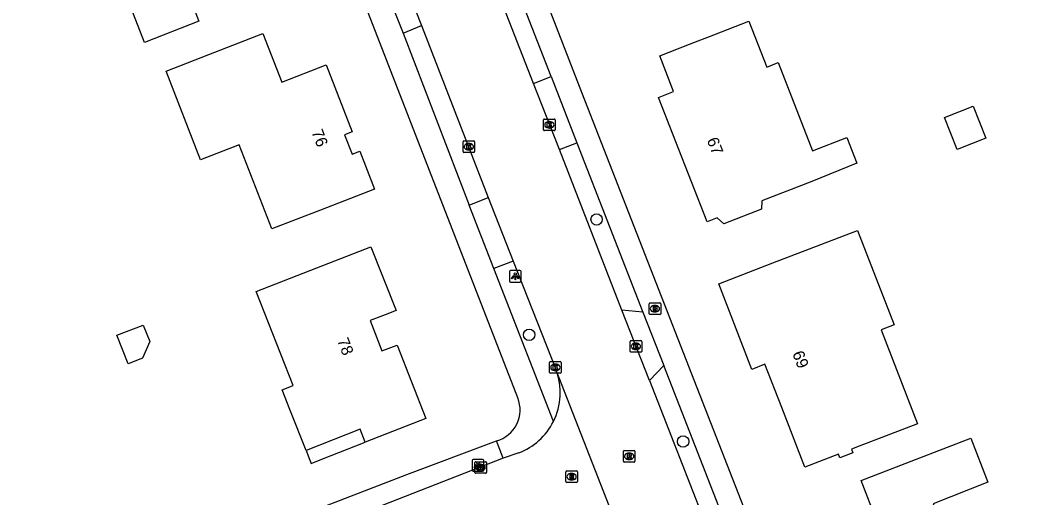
# Model space of a CAD drawing. Extents: x 157321 to 158827, y 386650 to 388532.
# Drawn here: x 158167.1 to 158253.3, y 387023.2 to 387064.3 of the extents above; entities that cross this region are included whole.
import ezdxf

# ---------------------------------------------------------------- set-up
doc = ezdxf.new("R2010")
doc.units = 0
for name, color, linetype in [('IMGEO_Boom', 7, 'Continuous'), ('IMGEO_Brandkraan', 7, 'Continuous'), ('IMGEO_Groenvoorziening', 7, 'Continuous'), ('IMGEO_Hek', 7, 'Continuous'), ('IMGEO_Kolk', 7, 'Continuous'), ('IMGEO_Lichtpunt', 7, 'Continuous'), ('IMGEO_Pand', 7, 'Continuous'), ('IMGEO_Pand_nummerreeks', 7, 'Continuous'), ('IMGEO_Pand_overbouw', 7, 'Continuous'), ('IMGEO_Rijbaan_lokaal_gesloten', 7, 'Continuous'), ('IMGEO_Rioolput', 7, 'Continuous'), ('IMGEO_Voetpad_open', 7, 'Continuous')]:
    doc.layers.add(name, color=color, linetype=linetype)

msp = doc.modelspace()

# ---------------------------------------------------------------- linework, layer by layer
at = {"layer": 'IMGEO_Boom'}
for centre in [(158216.746, 387047.149), (158210.932, 387037.217), (158224.196, 387028.029)]:
    msp.add_circle(centre, 0.489, dxfattribs=at)
at = {"layer": 'IMGEO_Brandkraan'}
for p, q in [((158221.265, 387039.034), (158221.265, 387039.886)), ((158221.34, 387039.96), (158222.192, 387039.96)), ((158221.753, 387039.74), (158221.778, 387039.74)), ((158222.266, 387039.886), (158222.266, 387039.034)), ((158222.192, 387038.96), (158221.34, 387038.96)), ((158221.776, 387039.18), (158221.751, 387039.18))]:
    msp.add_line(p, q, dxfattribs=at)
for points in [[(158221.265, 387039.034), (158221.265, 387039.886)], [(158221.34, 387039.96), (158222.192, 387039.96)], [(158221.613, 387039.66), (158221.613, 387039.26), (158221.826, 387039.26)], [(158221.844, 387039.66), (158221.613, 387039.66)], [(158221.792, 387039.579), (158221.738, 387039.579), (158221.738, 387039.503)], [(158221.738, 387039.503), (158221.791, 387039.503)], [(158221.8, 387039.427), (158221.738, 387039.427), (158221.738, 387039.346)], [(158222.266, 387039.886), (158222.266, 387039.034)], [(158222.192, 387038.96), (158221.34, 387038.96)], [(158221.738, 387039.346), (158221.8, 387039.346)]]:
    msp.add_lwpolyline(points, dxfattribs=at)
for centre, radius, start, end in [((158221.342, 387039.884), 0.0765, 91.55205, 178.44795), ((158221.342, 387039.884), 0.0765, 91.55205, 178.44795), ((158221.793, 387039.541), 0.0379, 267.82845, 90.93552), ((158221.801, 387039.386), 0.0404, 269.87594, 90.50774), ((158221.848, 387039.515), 0.145, 59.4692, 91.53667), ((158221.873, 387039.562), 0.0922, 285.51372, 58.15012), ((158221.878, 387039.37), 0.105, 301.31148, 78.98903), ((158222.19, 387039.884), 0.0765, 1.55205, 88.44795), ((158222.19, 387039.884), 0.0765, 1.55205, 88.44795), ((158221.342, 387039.036), 0.0765, 181.55205, 268.44795), ((158221.342, 387039.036), 0.0765, 181.55205, 268.44795), ((158221.832, 387039.511), 0.251, 268.66757, 293.53466), ((158222.19, 387039.036), 0.0765, 271.55205, 358.44795), ((158222.19, 387039.036), 0.0765, 271.55205, 358.44795)]:
    msp.add_arc(centre, radius, start, end, dxfattribs=at)
for centre, major_axis, ratio, start_param, end_param in [((158221.752, 387039.46), (-0.387, 0.002), 0.722429, 4.712389, 7.853982), ((158221.777, 387039.46), (-0.39, 0.002), 0.717154, 1.570796, 4.712389)]:
    msp.add_ellipse(centre, major_axis=major_axis, ratio=ratio, start_param=start_param, end_param=end_param, dxfattribs=at)
at = {"layer": 'IMGEO_Groenvoorziening'}
msp.add_lwpolyline([(158164.275, 387011.156), (158171.314, 387013.97), (158200.402, 387025.18), (158208.12, 387028.081)], dxfattribs=at)
at = {"layer": 'IMGEO_Hek'}
for points in [[(158200.402, 387025.18), (158208.12, 387028.081)], [(158171.314, 387013.97), (158200.402, 387025.18)]]:
    msp.add_lwpolyline(points, dxfattribs=at)
at = {"layer": 'IMGEO_Kolk'}
for p, q in [((158212.249, 387055.797), (158213.101, 387055.797)), ((158212.174, 387054.871), (158212.174, 387055.723)), ((158212.685, 387055.017), (158212.66, 387055.017)), ((158212.662, 387055.577), (158212.687, 387055.577)), ((158213.175, 387055.723), (158213.175, 387054.871)), ((158213.101, 387054.797), (158212.249, 387054.797)), ((158205.238, 387052.986), (158205.238, 387053.838)), ((158205.313, 387053.912), (158206.165, 387053.912)), ((158205.726, 387053.692), (158205.751, 387053.692)), ((158206.239, 387053.838), (158206.239, 387052.986)), ((158206.165, 387052.912), (158205.313, 387052.912)), ((158205.749, 387053.132), (158205.724, 387053.132)), ((158219.632, 387035.79), (158219.632, 387036.642)), ((158219.707, 387036.716), (158220.559, 387036.716)), ((158220.143, 387035.936), (158220.118, 387035.936)), ((158220.12, 387036.496), (158220.145, 387036.496)), ((158220.633, 387036.642), (158220.633, 387035.79)), ((158220.559, 387035.716), (158219.707, 387035.716)), ((158212.691, 387033.979), (158212.691, 387034.831)), ((158212.766, 387034.905), (158213.618, 387034.905)), ((158213.179, 387034.685), (158213.204, 387034.685)), ((158213.692, 387034.831), (158213.692, 387033.979)), ((158213.618, 387033.905), (158212.766, 387033.905)), ((158213.202, 387034.125), (158213.177, 387034.125)), ((158206.249, 387025.359), (158206.249, 387026.211)), ((158206.324, 387026.285), (158207.176, 387026.285)), ((158206.737, 387026.065), (158206.762, 387026.065)), ((158207.25, 387026.211), (158207.25, 387025.359)), ((158207.176, 387025.285), (158206.324, 387025.285)), ((158206.76, 387025.505), (158206.735, 387025.505))]:
    msp.add_line(p, q, dxfattribs=at)
for points in [[(158212.249, 387055.797), (158213.101, 387055.797)], [(158212.174, 387054.871), (158212.174, 387055.723)], [(158212.495, 387055.497), (158212.618, 387055.497), (158212.618, 387055.346), (158212.748, 387055.497), (158212.912, 387055.497), (158212.766, 387055.346), (158212.919, 387055.097), (158212.767, 387055.097), (158212.682, 387055.261), (158212.618, 387055.194), (158212.618, 387055.097), (158212.495, 387055.097), (158212.495, 387055.497)], [(158213.175, 387055.723), (158213.175, 387054.871)], [(158213.101, 387054.797), (158212.249, 387054.797)], [(158205.238, 387052.986), (158205.238, 387053.838)], [(158205.313, 387053.912), (158206.165, 387053.912)], [(158205.559, 387053.612), (158205.682, 387053.612), (158205.682, 387053.461), (158205.812, 387053.612), (158205.976, 387053.612), (158205.83, 387053.461), (158205.983, 387053.212), (158205.831, 387053.212), (158205.746, 387053.376), (158205.682, 387053.309), (158205.682, 387053.212), (158205.559, 387053.212), (158205.559, 387053.612)], [(158206.239, 387053.838), (158206.239, 387052.986)], [(158206.165, 387052.912), (158205.313, 387052.912)], [(158219.632, 387035.79), (158219.632, 387036.642)], [(158219.707, 387036.716), (158220.559, 387036.716)], [(158219.953, 387036.416), (158220.076, 387036.416), (158220.076, 387036.265), (158220.206, 387036.416), (158220.37, 387036.416), (158220.224, 387036.265), (158220.377, 387036.016), (158220.225, 387036.016), (158220.14, 387036.18), (158220.076, 387036.113), (158220.076, 387036.016), (158219.953, 387036.016), (158219.953, 387036.416)], [(158220.633, 387036.642), (158220.633, 387035.79)], [(158220.559, 387035.716), (158219.707, 387035.716)], [(158212.691, 387033.979), (158212.691, 387034.831)], [(158212.766, 387034.905), (158213.618, 387034.905)], [(158213.012, 387034.605), (158213.135, 387034.605), (158213.135, 387034.454), (158213.265, 387034.605), (158213.429, 387034.605), (158213.283, 387034.454), (158213.436, 387034.205), (158213.284, 387034.205), (158213.199, 387034.369), (158213.135, 387034.302), (158213.135, 387034.205), (158213.012, 387034.205), (158213.012, 387034.605)], [(158213.692, 387034.831), (158213.692, 387033.979)], [(158213.618, 387033.905), (158212.766, 387033.905)], [(158206.249, 387025.359), (158206.249, 387026.211)], [(158206.324, 387026.285), (158207.176, 387026.285)], [(158206.57, 387025.985), (158206.693, 387025.985), (158206.693, 387025.834), (158206.823, 387025.985), (158206.987, 387025.985), (158206.841, 387025.834), (158206.994, 387025.585), (158206.842, 387025.585), (158206.757, 387025.749), (158206.693, 387025.682), (158206.693, 387025.585), (158206.57, 387025.585), (158206.57, 387025.985)], [(158207.25, 387026.211), (158207.25, 387025.359)], [(158207.176, 387025.285), (158206.324, 387025.285)]]:
    msp.add_lwpolyline(points, dxfattribs=at)
for centre, start, end in [((158212.251, 387055.721), 91.55205, 178.44795), ((158212.251, 387055.721), 91.55205, 178.44795), ((158213.099, 387055.721), 1.55205, 88.44795), ((158213.099, 387055.721), 1.55205, 88.44795), ((158212.251, 387054.873), 181.55205, 268.44795), ((158212.251, 387054.873), 181.55205, 268.44795), ((158213.099, 387054.873), 271.55205, 358.44795), ((158213.099, 387054.873), 271.55205, 358.44795), ((158205.315, 387053.836), 91.55205, 178.44795), ((158205.315, 387053.836), 91.55205, 178.44795), ((158206.163, 387053.836), 1.55205, 88.44795), ((158206.163, 387053.836), 1.55205, 88.44795), ((158205.315, 387052.988), 181.55205, 268.44795), ((158205.315, 387052.988), 181.55205, 268.44795), ((158206.163, 387052.988), 271.55205, 358.44795), ((158206.163, 387052.988), 271.55205, 358.44795), ((158219.709, 387036.64), 91.55205, 178.44795), ((158219.709, 387036.64), 91.55205, 178.44795), ((158220.557, 387036.64), 1.55205, 88.44795), ((158220.557, 387036.64), 1.55205, 88.44795), ((158219.709, 387035.792), 181.55205, 268.44795), ((158219.709, 387035.792), 181.55205, 268.44795), ((158220.557, 387035.792), 271.55205, 358.44795), ((158220.557, 387035.792), 271.55205, 358.44795), ((158212.768, 387034.829), 91.55205, 178.44795), ((158212.768, 387034.829), 91.55205, 178.44795), ((158213.616, 387034.829), 1.55205, 88.44795), ((158213.616, 387034.829), 1.55205, 88.44795), ((158212.768, 387033.981), 181.55205, 268.44795), ((158212.768, 387033.981), 181.55205, 268.44795), ((158213.616, 387033.981), 271.55205, 358.44795), ((158213.616, 387033.981), 271.55205, 358.44795), ((158206.326, 387026.209), 91.55205, 178.44795), ((158206.326, 387026.209), 91.55205, 178.44795), ((158207.174, 387026.209), 1.55205, 88.44795), ((158207.174, 387026.209), 1.55205, 88.44795), ((158206.326, 387025.361), 181.55205, 268.44795), ((158206.326, 387025.361), 181.55205, 268.44795), ((158207.174, 387025.361), 271.55205, 358.44795), ((158207.174, 387025.361), 271.55205, 358.44795)]:
    msp.add_arc(centre, 0.0765, start, end, dxfattribs=at)
for centre, major_axis, ratio, start_param, end_param in [((158212.661, 387055.297), (-0.387, 0.002), 0.722429, 4.712389, 7.853982), ((158212.686, 387055.297), (-0.39, 0.002), 0.717154, 1.570796, 4.712389), ((158205.725, 387053.412), (-0.387, 0.002), 0.722429, 4.712389, 7.853982), ((158205.75, 387053.412), (-0.39, 0.002), 0.717154, 1.570796, 4.712389), ((158220.119, 387036.216), (-0.387, 0.002), 0.722429, 4.712389, 7.853982), ((158220.144, 387036.216), (-0.39, 0.002), 0.717154, 1.570796, 4.712389), ((158213.178, 387034.405), (-0.387, 0.002), 0.722429, 4.712389, 7.853982), ((158213.203, 387034.405), (-0.39, 0.002), 0.717154, 1.570796, 4.712389), ((158206.736, 387025.785), (-0.387, 0.002), 0.722429, 4.712389, 7.853982), ((158206.761, 387025.785), (-0.39, 0.002), 0.717154, 1.570796, 4.712389)]:
    msp.add_ellipse(centre, major_axis=major_axis, ratio=ratio, start_param=start_param, end_param=end_param, dxfattribs=at)
at = {"layer": 'IMGEO_Lichtpunt'}
for p, q in [((158209.241, 387042.655), (158209.241, 387041.848)), ((158209.241, 387042.655), (158209.241, 387041.848)), ((158210.143, 387042.75), (158209.335, 387042.75)), ((158210.143, 387042.75), (158209.335, 387042.75)), ((158210.237, 387041.848), (158210.237, 387042.655)), ((158210.237, 387041.848), (158210.237, 387042.655)), ((158209.335, 387041.754), (158210.143, 387041.754)), ((158209.335, 387041.754), (158210.143, 387041.754)), ((158206.924, 387026.474), (158206.116, 387026.474)), ((158206.924, 387026.474), (158206.116, 387026.474)), ((158206.022, 387026.379), (158206.022, 387025.572)), ((158206.022, 387026.379), (158206.022, 387025.572)), ((158207.018, 387025.572), (158207.018, 387026.379)), ((158207.018, 387025.572), (158207.018, 387026.379)), ((158206.116, 387025.478), (158206.924, 387025.478)), ((158206.116, 387025.478), (158206.924, 387025.478))]:
    msp.add_line(p, q, dxfattribs=at)
for points in [[(158209.615, 387042.319), (158209.654, 387042.291), (158209.466, 387042.029), (158209.428, 387042.056), (158209.615, 387042.319)], [(158209.717, 387042.271), (158209.764, 387042.271), (158209.764, 387041.949), (158209.717, 387041.949), (158209.717, 387042.271)], [(158209.827, 387042.291), (158209.865, 387042.318), (158210.052, 387042.056), (158210.013, 387042.028), (158209.827, 387042.291)], [(158206.396, 387026.043), (158206.435, 387026.015), (158206.247, 387025.753), (158206.209, 387025.78), (158206.396, 387026.043)], [(158206.498, 387025.995), (158206.545, 387025.995), (158206.545, 387025.673), (158206.498, 387025.673), (158206.498, 387025.995)], [(158206.608, 387026.015), (158206.646, 387026.042), (158206.833, 387025.78), (158206.794, 387025.752), (158206.608, 387026.015)]]:
    msp.add_lwpolyline(points, dxfattribs=at)
for centre in [(158209.74, 387042.453), (158206.521, 387026.177)]:
    msp.add_circle(centre, 0.0994, dxfattribs=at)
for centre, start, end in [((158209.335, 387042.655), 90, 180), ((158209.335, 387042.655), 90, 180), ((158210.143, 387042.655), 0, 90), ((158210.143, 387042.655), 0, 90), ((158209.335, 387041.848), 180, 270), ((158209.335, 387041.848), 180, 270), ((158210.143, 387041.848), 270, 0), ((158210.143, 387041.848), 270, 360), ((158206.116, 387026.379), 90, 180), ((158206.116, 387026.379), 90, 180), ((158206.924, 387026.379), 0, 90), ((158206.924, 387026.379), 0, 90), ((158206.116, 387025.572), 180, 270), ((158206.116, 387025.572), 180, 270), ((158206.924, 387025.572), 270, 0), ((158206.924, 387025.572), 270, 360)]:
    msp.add_arc(centre, 0.0946, start, end, dxfattribs=at)
at = {"layer": 'IMGEO_Pand'}
for points in [[(158180.919, 387079.128), (158182.888, 387074.067), (158187.406, 387075.824), (158188.819, 387072.194), (158187.699, 387071.753), (158189.187, 387067.922), (158184.527, 387066.11), (158182.102, 387065.167), (158182.475, 387064.21), (158177.811, 387062.396), (158175.705, 387067.813), (158177.358, 387068.456), (158174.221, 387076.522), (158176.26, 387077.315), (158180.919, 387079.128)], [(158239.172, 387051.986), (158235.27, 387050.43), (158230.972, 387048.764), (158230.945, 387048.036), (158227.7, 387046.757), (158227.144, 387047.28), (158226.275, 387046.944), (158223.573, 387053.843), (158222.078, 387057.659), (158223.374, 387058.161), (158222.182, 387061.247), (158224.757, 387062.242), (158226.847, 387063.049), (158229.87, 387064.217), (158231.416, 387060.27), (158232.386, 387060.651), (158235.353, 387053.05), (158238.306, 387054.203), (158239.172, 387051.986)], [(158179.653, 387059.92), (158183.344, 387061.351), (158188.005, 387063.158), (158189.628, 387058.973), (158193.441, 387060.451), (158195.686, 387054.692), (158195.034, 387054.438), (158195.688, 387052.761), (158196.34, 387053.015), (158197.61, 387049.753), (158192.949, 387047.946), (158188.774, 387046.327), (158185.962, 387053.582), (158182.613, 387052.284), (158179.653, 387059.92)], [(158250.286, 387054.151), (158247.817, 387053.166), (158246.716, 387055.927), (158249.185, 387056.911), (158250.286, 387054.151)], [(158242.362, 387038.076), (158241.247, 387037.642), (158244.393, 387029.555), (158239.359, 387027.615), (158238.687, 387027.356), (158238.805, 387027.052), (158237.686, 387026.618), (158237.567, 387026.925), (158234.693, 387025.817), (158232.699, 387030.94), (158231.245, 387034.674), (158230.127, 387034.239), (158227.269, 387041.602), (158231.935, 387043.401), (158239.204, 387046.204), (158242.362, 387038.076)], [(158192.644, 387042.974), (158197.299, 387044.799), (158199.469, 387039.304), (158198.533, 387038.945), (158197.238, 387038.449), (158198.245, 387035.826), (158199.558, 387036.329), (158202.034, 387030.01), (158196.811, 387027.963), (158196.374, 387029.08), (158191.717, 387027.254), (158190.33, 387030.793), (158189.668, 387032.482), (158190.598, 387032.846), (158187.429, 387040.93), (158192.644, 387042.974)], [(158177.686, 387038.058), (158178.247, 387036.627), (158177.625, 387035.189), (158176.391, 387034.705), (158175.424, 387037.172), (158177.686, 387038.058)], [(158253.3, 387012.648), (158247.613, 387008.304), (158246.067, 387012.374), (158244.316, 387011.689), (158240.302, 387010.118), (158239.659, 387009.867), (158238.372, 387013.142), (158237.638, 387012.846), (158236.522, 387015.733), (158237.243, 387016.015), (158235.983, 387019.284), (158240.893, 387021.176), (158239.547, 387024.67), (158244.213, 387026.468), (158248.967, 387028.3), (158250.438, 387024.529), (158245.722, 387022.667), (158246.488, 387020.727), (158247.909, 387021.288), (158249.833, 387016.414), (158248.393, 387015.867), (158249.113, 387013.971), (158252.333, 387015.194), (158253.3, 387012.648)]]:
    msp.add_lwpolyline(points, dxfattribs=at)
at = {"layer": 'IMGEO_Pand_overbouw'}
msp.add_lwpolyline([(158191.717, 387027.254), (158192.046, 387026.417), (158192.155, 387026.137), (158193.078, 387026.499), (158196.811, 387027.963), (158196.374, 387029.08)], close=True, dxfattribs=at)
at = {"layer": 'IMGEO_Rijbaan_lokaal_gesloten'}
for points in [[(158211.307, 387058.859), (158204.1, 387077.351)], [(158200.191, 387067.589), (158201.673, 387063.843)], [(158201.673, 387063.843), (158207.412, 387049.027)], [(158213.536, 387053.162), (158211.307, 387058.859)], [(158218.932, 387039.336), (158213.536, 387053.162)], [(158207.412, 387049.027), (158209.565, 387043.566)], [(158209.565, 387043.566), (158213.249, 387034.182)], [(158221.295, 387033.291), (158218.932, 387039.336)], [(158219.507, 387018.022), (158219.519, 387018.157), (158213.249, 387034.182)], [(158221.295, 387033.291), (158226.211, 387020.702)], [(158208.687, 387026.576), (158178.74, 387014.873), (158164.899, 387009.476)], [(158210.032, 387027.043), (158208.687, 387026.576)]]:
    msp.add_lwpolyline(points, dxfattribs=at)
for centre, radius, start, end in [((158208.07, 387032.223), 5.538, 333.4209, 20.72163), ((158208.068, 387032.222), 5.539, 290.77005, 333.43686)]:
    msp.add_arc(centre, radius, start, end, dxfattribs=at)
at = {"layer": 'IMGEO_Rioolput'}
for p, q in [((158219.049, 387026.328), (158219.049, 387027.18)), ((158219.124, 387027.254), (158219.976, 387027.254)), ((158219.56, 387026.474), (158219.535, 387026.474)), ((158219.537, 387027.034), (158219.562, 387027.034)), ((158220.05, 387027.18), (158220.05, 387026.328)), ((158219.976, 387026.254), (158219.124, 387026.254)), ((158214.092, 387024.569), (158214.092, 387025.421)), ((158214.167, 387025.495), (158215.019, 387025.495)), ((158214.603, 387024.715), (158214.578, 387024.715)), ((158214.58, 387025.275), (158214.605, 387025.275)), ((158215.093, 387025.421), (158215.093, 387024.569)), ((158215.019, 387024.495), (158214.167, 387024.495))]:
    msp.add_line(p, q, dxfattribs=at)
for points in [[(158219.049, 387026.328), (158219.049, 387027.18)], [(158219.124, 387027.254), (158219.976, 387027.254)], [(158219.638, 387026.952), (158219.386, 387026.954), (158219.386, 387026.554)], [(158219.386, 387026.554), (158219.51, 387026.554), (158219.51, 387026.716), (158219.521, 387026.716)], [(158219.564, 387026.873), (158219.51, 387026.873), (158219.51, 387026.792)], [(158219.51, 387026.792), (158219.562, 387026.792)], [(158219.568, 387026.687), (158219.639, 387026.554), (158219.779, 387026.554), (158219.714, 387026.68)], [(158220.05, 387027.18), (158220.05, 387026.328)], [(158219.976, 387026.254), (158219.124, 387026.254)], [(158214.092, 387024.569), (158214.092, 387025.421)], [(158214.167, 387025.495), (158215.019, 387025.495)], [(158214.681, 387025.193), (158214.429, 387025.195), (158214.429, 387024.795)], [(158214.429, 387024.795), (158214.553, 387024.795), (158214.553, 387024.957), (158214.564, 387024.957)], [(158214.607, 387025.114), (158214.553, 387025.114), (158214.553, 387025.033)], [(158214.553, 387025.033), (158214.605, 387025.033)], [(158214.611, 387024.928), (158214.682, 387024.795), (158214.822, 387024.795), (158214.757, 387024.921)], [(158215.093, 387025.421), (158215.093, 387024.569)], [(158215.019, 387024.495), (158214.167, 387024.495)]]:
    msp.add_lwpolyline(points, dxfattribs=at)
for centre, radius, start, end in [((158219.126, 387027.178), 0.0765, 91.55205, 178.44795), ((158219.126, 387027.178), 0.0765, 91.55205, 178.44795), ((158219.52, 387026.663), 0.0533, 26.02933, 88.69889), ((158219.546, 387026.981), 0.19, 274.7715, 282.96867), ((158219.57, 387026.777), 0.0964, 77.00612, 93.18647), ((158219.584, 387026.834), 0.0378, 276.66336, 79.67722), ((158219.637, 387026.842), 0.109, 350.36119, 89.41601), ((158219.635, 387026.842), 0.112, 277.58423, 350.98172), ((158219.619, 387026.627), 0.108, 29.51342, 73.79051), ((158219.974, 387027.178), 0.0765, 1.55205, 88.44795), ((158219.974, 387027.178), 0.0765, 1.55205, 88.44795), ((158219.126, 387026.33), 0.0765, 181.55205, 268.44795), ((158219.126, 387026.33), 0.0765, 181.55205, 268.44795), ((158219.974, 387026.33), 0.0765, 271.55205, 358.44795), ((158219.974, 387026.33), 0.0765, 271.55205, 358.44795), ((158214.169, 387025.419), 0.0765, 91.55205, 178.44795), ((158214.169, 387025.419), 0.0765, 91.55205, 178.44795), ((158214.563, 387024.904), 0.0533, 26.02933, 88.69889), ((158214.589, 387025.222), 0.19, 274.7715, 282.96867), ((158214.613, 387025.018), 0.0964, 77.00612, 93.18647), ((158214.627, 387025.075), 0.0378, 276.66336, 79.67722), ((158214.68, 387025.083), 0.109, 350.36119, 89.41601), ((158214.678, 387025.083), 0.112, 277.58423, 350.98172), ((158214.662, 387024.868), 0.108, 29.51342, 73.79051), ((158215.017, 387025.419), 0.0765, 1.55205, 88.44795), ((158215.017, 387025.419), 0.0765, 1.55205, 88.44795), ((158214.169, 387024.571), 0.0765, 181.55205, 268.44795), ((158214.169, 387024.571), 0.0765, 181.55205, 268.44795), ((158215.017, 387024.571), 0.0765, 271.55205, 358.44795), ((158215.017, 387024.571), 0.0765, 271.55205, 358.44795)]:
    msp.add_arc(centre, radius, start, end, dxfattribs=at)
for centre, major_axis, ratio, start_param, end_param in [((158219.536, 387026.754), (-0.387, 0.002), 0.722429, 4.712389, 7.853982), ((158219.561, 387026.754), (-0.39, 0.002), 0.717154, 1.570796, 4.712389), ((158214.579, 387024.995), (-0.387, 0.002), 0.722429, 4.712389, 7.853982), ((158214.604, 387024.995), (-0.39, 0.002), 0.717154, 1.570796, 4.712389)]:
    msp.add_ellipse(centre, major_axis=major_axis, ratio=ratio, start_param=start_param, end_param=end_param, dxfattribs=at)
at = {"layer": 'IMGEO_Voetpad_open'}
for points in [[(158192.002, 387118.576), (158215.25, 387058.634), (158234.598, 387009.079), (158235.235, 387007.476)], [(158209.958, 387031.786), (158185.382, 387095.063)], [(158212.819, 387059.448), (158205.614, 387077.958)], [(158198.594, 387066.956), (158200.068, 387063.193)], [(158200.068, 387063.193), (158201.673, 387063.843)], [(158200.068, 387063.193), (158205.771, 387048.391)], [(158211.307, 387058.859), (158212.819, 387059.448)], [(158212.819, 387059.448), (158215.039, 387053.749)], [(158213.536, 387053.162), (158215.039, 387053.749)], [(158215.039, 387053.749), (158220.735, 387039.162)], [(158205.771, 387048.391), (158207.412, 387049.027)], [(158207.897, 387042.911), (158205.771, 387048.391)], [(158209.565, 387043.566), (158207.897, 387042.911)], [(158213.022, 387029.745), (158207.897, 387042.911)], [(158220.735, 387039.162), (158218.932, 387039.336)], [(158220.735, 387039.162), (158222.528, 387034.561)], [(158222.528, 387034.561), (158221.295, 387033.291)], [(158233.401, 387006.768), (158232.88, 387008.083), (158222.528, 387034.561)], [(158208.687, 387026.576), (158208.12, 387028.081)]]:
    msp.add_lwpolyline(points, dxfattribs=at)
msp.add_arc((158207.368, 387030.762), 2.785, 285.66086, 21.56837, dxfattribs=at)

# ---------------------------------------------------------------- texts
at = {"layer": 'IMGEO_Pand_nummerreeks'}
for s, rotation, p in [('76', 291.29081, (158192.169, 387054.681)), ('67', 291.38998, (158226.221, 387053.99)), ('78', 291.00237, (158194.384, 387036.731)), ('69', 291.27079, (158233.585, 387035.608))]:
    msp.add_text(s, height=1, rotation=rotation, dxfattribs=at).set_placement(p)

doc.saveas('drawing.dxf')
